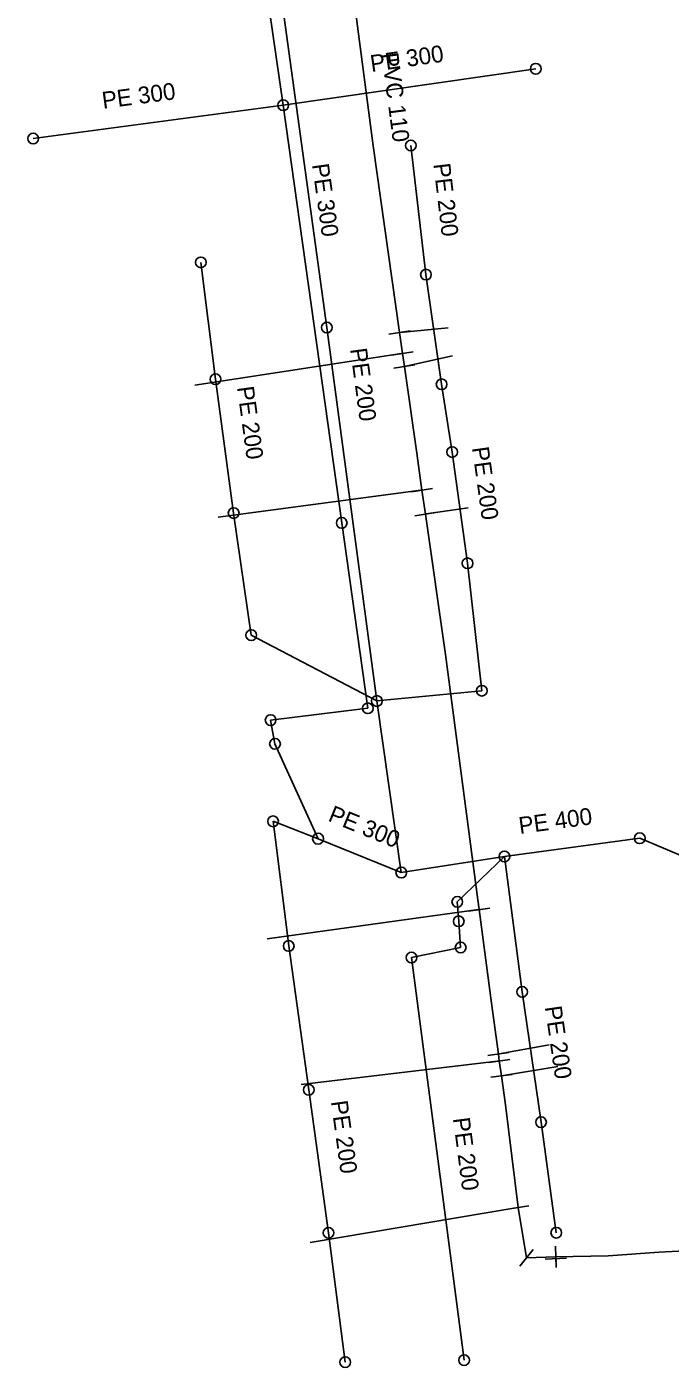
# Model space of a CAD drawing. Extents: x -867696 to -865033, y -1042522 to -1039817.
# Drawn here: x -866686.6 to -866610.2, y -1040211.3 to -1040051.9 of the extents above; entities that cross this region are included whole.
import ezdxf

# ---------------------------------------------------------------- set-up
doc = ezdxf.new("R2010")
doc.units = 0
for name, color, linetype in [('KN - destova', 7, 'Continuous'), ('KN - jednotna', 7, 'Continuous'), ('KN - popis material', 7, 'Continuous'), ('KN - sachta komora', 7, 'Continuous'), ('KN - splaskova', 7, 'Continuous'), ('Level 1', 7, 'Continuous'), ('V - armatura', 7, 'Continuous'), ('V - hydrant', 7, 'Continuous'), ('V - popis material', 7, 'Continuous'), ('V - pripojka', 7, 'Continuous'), ('V - rozvadeci', 7, 'Continuous')]:
    doc.layers.add(name, color=color, linetype=linetype)

# ---------------------------------------------------------------- blocks, each defined once
blk = doc.blocks.new('100.M')
at = {"layer": 'Level 1'}
blk.add_circle((0, 0), 1.27, dxfattribs=at)
blk = doc.blocks.new('147')
at = {"layer": 'Level 1'}
blk.add_line((0, 1.27), (0, -1.27), dxfattribs=at)
blk = doc.blocks.new('150')
at = {"layer": 'Level 1'}
blk.add_line((0, 1.27), (0, -1.27), dxfattribs=at)

msp = doc.modelspace()

# ---------------------------------------------------------------- linework, layer by layer
at = {"layer": 'KN - destova'}
for points in [[(-866659.46, -1040038.44), (-866656.16, -1040061.19)], [(-866656.16, -1040061.19), (-866626.17, -1040056.86)], [(-866656.16, -1040061.19), (-866685.86, -1040065.15)], [(-866656.16, -1040061.19), (-866649.22, -1040110.82)], [(-866649.22, -1040110.82), (-866646.12, -1040132.85)], [(-866646.12, -1040132.85), (-866657.66, -1040134.25)], [(-866657.66, -1040134.25), (-866657.14, -1040137.07)], [(-866657.14, -1040137.07), (-866652.02, -1040148.34)], [(-866635.49, -1040155.85), (-866629.89, -1040150.46)], [(-866635.32, -1040158.16), (-866635.49, -1040155.85)], [(-866635.09, -1040161.27), (-866635.32, -1040158.16)], [(-866640.93, -1040162.47), (-866635.09, -1040161.27)], [(-866634.68, -1040210.3), (-866640.93, -1040162.47)]]:
    msp.add_lwpolyline(points, dxfattribs=at)
at = {"layer": 'KN - jednotna'}
for points in [[(-866642.14, -1040152.37), (-866652.02, -1040148.34)], [(-866613.82, -1040148.29), (-866629.89, -1040150.46)], [(-866603.12, -1040152.81), (-866613.82, -1040148.29)], [(-866629.89, -1040150.46), (-866642.14, -1040152.37)]]:
    msp.add_lwpolyline(points, dxfattribs=at)
at = {"layer": 'KN - splaskova'}
for points in [[(-866657.27, -1040041.83), (-866650.99, -1040087.61)], [(-866641.01, -1040065.97), (-866639.21, -1040081.32)], [(-866665.95, -1040079.86), (-866664.21, -1040093.75)], [(-866639.21, -1040081.32), (-866637.35, -1040094.35)], [(-866650.99, -1040087.61), (-866645.04, -1040131.98)], [(-866664.21, -1040093.75), (-866662.05, -1040109.65)], [(-866637.35, -1040094.35), (-866636.1, -1040102.4)], [(-866636.1, -1040102.4), (-866634.27, -1040115.62)], [(-866662.05, -1040109.65), (-866659.96, -1040124.16)], [(-866634.27, -1040115.62), (-866632.57, -1040130.76)], [(-866659.96, -1040124.16), (-866645.04, -1040131.98)], [(-866632.57, -1040130.76), (-866645.04, -1040131.98)], [(-866645.04, -1040131.98), (-866642.14, -1040152.37)], [(-866652.02, -1040148.34), (-866657.37, -1040146.28)], [(-866657.37, -1040146.28), (-866655.51, -1040161.09)], [(-866629.89, -1040150.46), (-866627.79, -1040166.54)], [(-866655.51, -1040161.09), (-866653.13, -1040178.18)], [(-866627.79, -1040166.54), (-866625.54, -1040182.03)], [(-866653.13, -1040178.18), (-866650.79, -1040195.18)], [(-866625.54, -1040182.03), (-866623.73, -1040195.16)], [(-866650.79, -1040195.18), (-866648.8, -1040210.54)]]:
    msp.add_lwpolyline(points, dxfattribs=at)
at = {"layer": 'V - pripojka'}
for points in [[(-866642.35, -1040088.21), (-866642.259, -1040088.197), (-866636.58, -1040087.63)], [(-866641.99, -1040090.69), (-866642.122, -1040090.704), (-866666.65, -1040094.46)], [(-866641.77, -1040092.23), (-866641.604, -1040092.194), (-866636.04, -1040090.97)], [(-866639.69, -1040106.92), (-866639.814, -1040106.936), (-866663.87, -1040110.13)], [(-866639.28, -1040109.77), (-866639.2, -1040109.757), (-866634.2, -1040109.02)], [(-866632.9, -1040156.76), (-866632.988, -1040156.77), (-866658.08, -1040160.26)], [(-866630.61, -1040173.93), (-866630.52, -1040173.908), (-866624.56, -1040172.83)], [(-866630.5, -1040174.74), (-866630.773, -1040174.768), (-866654.03, -1040177.57)], [(-866630.25, -1040176.52), (-866623.54, -1040175.41)], [(-866628.25, -1040192.18), (-866628.518, -1040192.215), (-866652.95, -1040196.33)], [(-866623.78, -1040198.02), (-866623.77, -1040198.25), (-866623.75, -1040198.58)]]:
    msp.add_lwpolyline(points, dxfattribs=at)
at = {"layer": 'V - rozvadeci'}
for points in [[(-866647.78, -1040048.43), (-866645.5, -1040066.02), (-866642.35, -1040088.21)], [(-866642.35, -1040088.21), (-866641.99, -1040090.69)], [(-866641.99, -1040090.69), (-866641.77, -1040092.23)], [(-866641.77, -1040092.23), (-866640.31, -1040102.54), (-866639.69, -1040106.92)], [(-866639.69, -1040106.92), (-866639.28, -1040109.77)], [(-866639.28, -1040109.77), (-866636.9, -1040126.47), (-866633.05, -1040155.61), (-866632.9, -1040156.76)], [(-866632.9, -1040156.76), (-866631.43, -1040167.88), (-866630.61, -1040173.93)], [(-866630.61, -1040173.93), (-866630.5, -1040174.74)], [(-866630.5, -1040174.74), (-866630.25, -1040176.52)], [(-866630.25, -1040176.52), (-866629.78, -1040179.98), (-866628.25, -1040192.18)], [(-866628.25, -1040192.18), (-866627.27, -1040198.13)], [(-866627.27, -1040198.13), (-866623.78, -1040198.02)], [(-866623.78, -1040198.02), (-866617.56, -1040197.9), (-866611.53, -1040197.46), (-866605.39, -1040197.15)]]:
    msp.add_lwpolyline(points, dxfattribs=at)

# ---------------------------------------------------------------- block references
at = {"layer": 'KN - sachta komora'}
for p, xscale, yscale, rotation in [((-866626.17, -1040056.86), 0.5041888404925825, 0.5041888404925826, 11.626378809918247), ((-866656.16, -1040061.19), 0.49999999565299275, 0.4999999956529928, -127.00000193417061), ((-866685.86, -1040065.15), 0.5046025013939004, 0.5046025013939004, -168.88308178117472), ((-866641.01, -1040065.97), 0.500095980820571, 0.500095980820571, -82.91099886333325), ((-866665.95, -1040079.86), 0.49999999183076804, 0.49999999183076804, -81.99999961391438), ((-866639.21, -1040081.32), 0.49999999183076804, 0.49999999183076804, 98.00000038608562), ((-866650.99, -1040087.61), 0.49999999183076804, 0.49999999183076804, 98.00000038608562), ((-866664.21, -1040093.75), 0.49999999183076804, 0.49999999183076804, 98.00000038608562), ((-866637.35, -1040094.35), 0.5000000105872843, 0.5000000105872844, 98.99999960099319), ((-866636.1, -1040102.4), 0.5000000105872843, 0.5000000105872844, 98.99999960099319), ((-866662.05, -1040109.65), 0.49999999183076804, 0.49999999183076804, 98.00000038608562), ((-866649.22, -1040110.82), 0.49999999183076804, 0.49999999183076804, 98.00000038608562), ((-866634.27, -1040115.62), 0.49999999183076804, 0.49999999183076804, 98.00000038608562), ((-866659.96, -1040124.16), 0.5000000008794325, 0.5000000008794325, 125.99999933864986), ((-866632.57, -1040130.76), 0.5000000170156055, 0.5000000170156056, -128.00000040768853), ((-866645.04, -1040131.98), 0.5030333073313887, 0.5030333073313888, 167.3452647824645), ((-866646.12, -1040132.85), 0.49999999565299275, 0.4999999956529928, -127.00000193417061), ((-866657.66, -1040134.25), 0.5000000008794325, 0.5000000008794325, 54.00000066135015), ((-866657.14, -1040137.07), 0.500000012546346, 0.5000000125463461, 108.00000002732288), ((-866657.37, -1040146.28), 0.500000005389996, 0.5000000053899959, 38.9999989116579), ((-866652.02, -1040148.34), 0.5137536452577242, 0.513753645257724, 155.31089431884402), ((-866613.82, -1040148.29), 0.5049058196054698, 0.5049058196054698, 169.38969821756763), ((-866629.89, -1040150.46), 0.5041888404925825, 0.5041888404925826, -168.37362119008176), ((-866642.14, -1040152.37), 0.5005608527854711, 0.5005608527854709, 173.41739016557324), ((-866635.49, -1040155.85), 0.4999999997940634, 0.4999999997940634, 69.99999934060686), ((-866635.32, -1040158.16), 0.500000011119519, 0.5000000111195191, 94.99999998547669), ((-866655.51, -1040161.09), 0.49999999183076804, 0.49999999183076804, 98.00000038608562), ((-866640.93, -1040162.47), 0.5000000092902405, 0.5000000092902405, 54.99999976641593), ((-866635.09, -1040161.27), 0.49999999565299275, 0.4999999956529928, -127.00000193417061), ((-866627.79, -1040166.54), 0.49999999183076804, 0.49999999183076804, 98.00000038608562), ((-866653.13, -1040178.18), 0.49999999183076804, 0.49999999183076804, 98.00000038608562), ((-866625.54, -1040182.03), 0.5000000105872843, 0.5000000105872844, 98.99999960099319), ((-866650.79, -1040195.18), 0.49999999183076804, 0.49999999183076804, 98.00000038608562), ((-866623.73, -1040195.16), 0.49999999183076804, 0.49999999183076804, -81.99999961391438), ((-866634.68, -1040210.3), 0.49999999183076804, 0.49999999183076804, 98.00000038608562), ((-866648.8, -1040210.54), 0.49999999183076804, 0.49999999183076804, -81.99999961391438)]:
    msp.add_blockref('100.M', p, dxfattribs=dict(at, xscale=xscale, yscale=yscale, rotation=rotation))
at = {"layer": 'V - armatura'}
for p, xscale, yscale, rotation in [((-866642.35, -1040088.21), 1.0000000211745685, 1.0000000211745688, 98.99999960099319), ((-866641.99, -1040090.69), 1.0000000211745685, 1.0000000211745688, 98.99999960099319), ((-866641.77, -1040092.23), 1.0000000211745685, 1.0000000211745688, 98.99999960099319), ((-866639.69, -1040106.92), 1.0000000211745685, 1.0000000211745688, 98.99999960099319), ((-866639.28, -1040109.77), 1.0000000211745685, 1.0000000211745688, 98.99999960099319), ((-866632.9, -1040156.76), 0.9999999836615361, 0.9999999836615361, 98.00000038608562), ((-866630.61, -1040173.93), 0.9999999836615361, 0.9999999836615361, 98.00000038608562), ((-866630.5, -1040174.74), 0.9999999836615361, 0.9999999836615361, 98.00000038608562), ((-866630.25, -1040176.52), 0.9999999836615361, 0.9999999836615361, 98.00000038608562), ((-866628.25, -1040192.18), 1.0000000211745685, 1.0000000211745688, 98.99999960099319), ((-866623.78, -1040198.02), 1.00000001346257, 1.0000000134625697, -178.0000000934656), ((-866627.27, -1040198.13), 1.000000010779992, 1.0000000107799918, 141.00000108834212)]:
    msp.add_blockref('147', p, dxfattribs=dict(at, xscale=xscale, yscale=yscale, rotation=rotation))
at = {"layer": 'V - hydrant', "xscale": 0.9999999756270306, "yscale": 0.9999999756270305, "rotation": -86.99999998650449}
msp.add_blockref('150', (-866623.77, -1040198.25), dxfattribs=at)

# ---------------------------------------------------------------- texts
at = {"layer": 'KN - popis material'}
for s, rotation, p in [('PE 300', 8.22, (-866645.685, -1040057.253)), ('PE 300', 7.59, (-866677.553, -1040061.621)), ('PE 300', 277.96, (-866652.751, -1040068.242)), ('PE 200', 276.69, (-866638.335, -1040068.178)), ('PE 200', 277.64, (-866648.226, -1040090.162)), ('PE 200', 277.74, (-866661.659, -1040094.7)), ('PE 200', 277.88, (-866633.748, -1040101.888)), ('PE 300', 337.81, (-866650.948, -1040146.185)), ('PE 400', 7.69, (-866628.06, -1040147.791)), ('PE 200', 278.26, (-866625.103, -1040168.338)), ('PE 200', 277.84, (-866650.516, -1040179.571)), ('PE 200', 277.44, (-866636.013, -1040181.575))]:
    msp.add_text(s, height=2, rotation=rotation, dxfattribs=at).set_placement(p)
at = {"layer": 'V - popis material'}
msp.add_text('PVC 110', height=2, rotation=277.39, dxfattribs=at).set_placement((-866644.501, -1040055.066))

doc.saveas('drawing.dxf')
